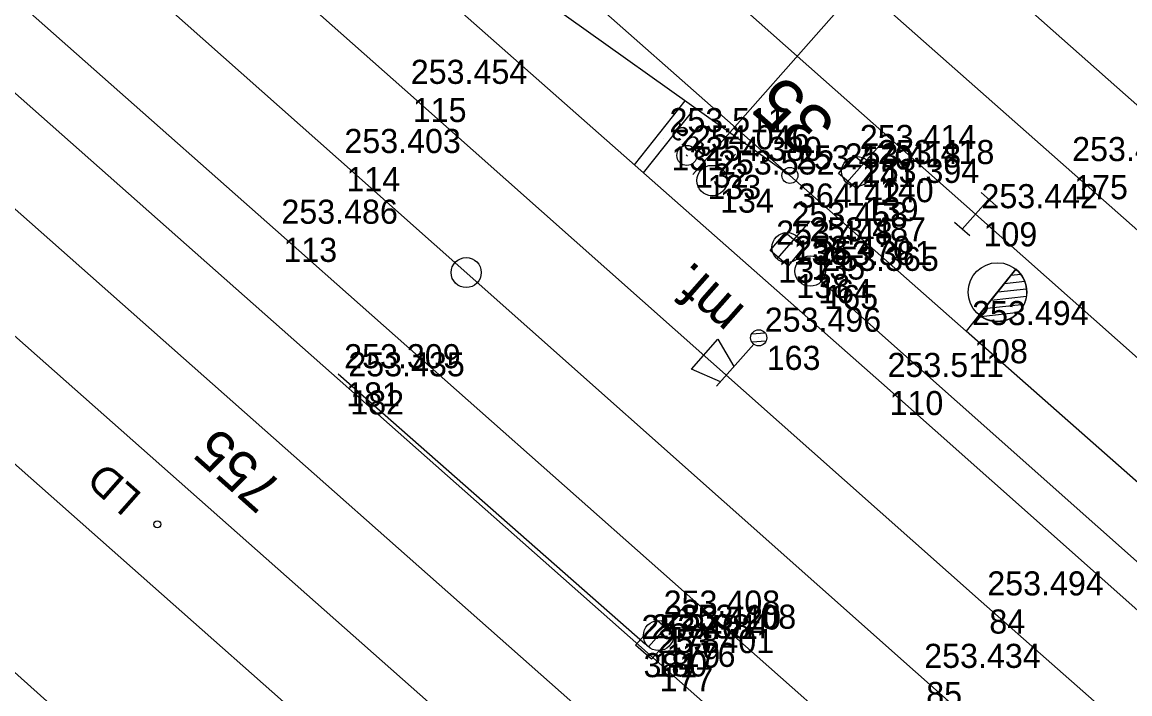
# Model space of a CAD drawing. Extents: x -496688 to -495455, y -1089309 to -1088026.
# Drawn here: x -496161.2 to -496106, y -1088523.5 to -1088490 of the extents above; entities that cross this region are included whole.
import ezdxf

# ---------------------------------------------------------------- set-up
doc = ezdxf.new("R2010")
doc.units = 0
for name, color, linetype in [('Vrstva 1', 7, 'Continuous'), ('Vrstva 12', 7, 'Continuous'), ('Vrstva 2', 7, 'Continuous'), ('Vrstva 23', 7, 'Continuous'), ('Vrstva 3', 7, 'Continuous'), ('Vrstva 33', 7, 'Continuous'), ('Vrstva 36', 7, 'Continuous'), ('Vrstva 47', 7, 'Continuous'), ('Vrstva 57', 7, 'Continuous'), ('Vrstva 59', 7, 'Continuous'), ('Vrstva 6', 7, 'Continuous'), ('Vrstva 60', 7, 'Continuous'), ('Vrstva 61', 7, 'Continuous'), ('Vrstva 7', 7, 'Continuous')]:
    doc.layers.add(name, color=color, linetype=linetype)

msp = doc.modelspace()

# ---------------------------------------------------------------- linework, layer by layer
at = {"layer": 'Vrstva 1'}
for points in [[(-496098.321, -1088532.14), (-496113.381, -1088518.859), (-496142.095, -1088493.38), (-496184.385, -1088455.93), (-496196.867, -1088444.876), (-496209.306, -1088433.861), (-496213.249, -1088430.329), (-496225.685, -1088419.311), (-496238.055, -1088408.352), (-496252.739, -1088395.349), (-496269.088, -1088380.829), (-496284.933, -1088366.798), (-496289.774, -1088362.518), (-496304.914, -1088349.103), (-496331.751, -1088325.354), (-496382.404, -1088280.635)], [(-496101.697, -1088535.642), (-496116.65, -1088522.36), (-496145.401, -1088496.824), (-496192.559, -1088454.988), (-496206.347, -1088442.759), (-496213.463, -1088436.447), (-496216.342, -1088433.89), (-496225.123, -1088426.139), (-496237.731, -1088415.01), (-496248.348, -1088406.17), (-496261.601, -1088395.991)], [(-495794.281, -1088769.662), (-495806.718, -1088758.644), (-495819.114, -1088747.662), (-495828.107, -1088739.648), (-495840.608, -1088728.579), (-495852.984, -1088717.621), (-495860.029, -1088711.42), (-495872.461, -1088700.397), (-495884.955, -1088689.319), (-495893.533, -1088681.721), (-495913.179, -1088664.263), (-495947.105, -1088634.191), (-495952.116, -1088629.76), (-495964.613, -1088618.686), (-495984.901, -1088600.717), (-495997.336, -1088589.715), (-496002.819, -1088584.884), (-496021.751, -1088568.167), (-496024.418, -1088565.811), (-496062.504, -1088532.205), (-496086.773, -1088510.767), (-496106.199, -1088493.629), (-496127.249, -1088474.987), (-496164.633, -1088441.927)], [(-496122.914, -1088497.64), (-496138.079, -1088486.834), (-496145.352, -1088481.632), (-496159.797, -1088471.287), (-496169.319, -1088464.468), (-496183.248, -1088454.488), (-496196.867, -1088444.876)], [(-495916.136, -1088667.962), (-495923.285, -1088661.656), (-495935.688, -1088650.668), (-495948.162, -1088639.613), (-495977.755, -1088613.379), (-495990.206, -1088602.384), (-496002.656, -1088591.386), (-496007.627, -1088586.973), (-496020.065, -1088575.979), (-496027.948, -1088569.009), (-496033.091, -1088564.46), (-496045.526, -1088553.442), (-496057.996, -1088542.394), (-496059.439, -1088541.128), (-496090.012, -1088514.139), (-496109.155, -1088497.226), (-496130.335, -1088478.506), (-496167.718, -1088445.393)], [(-496025.85, -1088577.242), (-496038.324, -1088566.223), (-496068.822, -1088539.309), (-496081.287, -1088528.275), (-496093.728, -1088517.263), (-496094.813, -1088516.301), (-496113.671, -1088499.573), (-496133.331, -1088482.129), (-496170.85, -1088448.892)], [(-496095.727, -1088521.63), (-496114.138, -1088505.396), (-496122.914, -1088497.64), (-496136.308, -1088485.801), (-496152.389, -1088471.491), (-496161.166, -1088463.737)], [(-496104.138, -1088539.66), (-496119.75, -1088525.847), (-496148.539, -1088500.347), (-496166.653, -1088484.334), (-496175.44, -1088476.59), (-496187.907, -1088465.601)], [(-496099.2, -1088524.988), (-496118.349, -1088507.977), (-496145.851, -1088483.696), (-496159.797, -1088471.287)], [(-496128.341, -1088534.994), (-496173.425, -1088495.115)], [(-496125.191, -1088531.455), (-496163.844, -1088497.265)], [(-496131.495, -1088538.579), (-496169.855, -1088504.648)]]:
    msp.add_lwpolyline(points, dxfattribs=at)
at = {"layer": 'Vrstva 12'}
for points in [[(-496120.488, -1088497.542), (-496119.728, -1088496.624), (-496118.831, -1088497.375), (-496119.584, -1088498.313), (-496120.488, -1088497.542)], [(-496123.895, -1088501.385), (-496123.131, -1088500.48), (-496122.24, -1088501.226), (-496122.991, -1088502.148), (-496123.895, -1088501.385)], [(-496130.602, -1088521.03), (-496129.5, -1088519.815), (-496128.699, -1088520.518), (-496129.801, -1088521.733), (-496130.602, -1088521.03)]]:
    msp.add_lwpolyline(points, dxfattribs=at)
at = {"layer": 'Vrstva 2'}
for p, q in [((-496113.495, -1088504.593), (-496111.658, -1088502.314)), ((-496111.658, -1088502.314), (-496113.494, -1088504.594)), ((-496111.897, -1088502.61), (-496111.423, -1088502.558)), ((-496112.229, -1088503.023), (-496111.22, -1088502.914)), ((-496112.896, -1088503.849), (-496111.13, -1088503.659)), ((-496112.562, -1088503.436), (-496111.126, -1088503.281)), ((-496113.229, -1088504.261), (-496111.242, -1088504.047)), ((-496113.496, -1088504.594), (-496114.138, -1088505.396)), ((-496113.494, -1088504.594), (-496113.495, -1088504.593)), ((-496113.402, -1088504.658), (-496111.514, -1088504.454))]:
    msp.add_line(p, q, dxfattribs=at)
for points in [[(-496114.138, -1088505.396), (-496122.914, -1088497.64), (-496136.308, -1088485.801)], [(-496122.914, -1088497.64), (-496138.079, -1088486.834)]]:
    msp.add_lwpolyline(points, dxfattribs=at)
for centre, radius in [((-496122.914, -1088497.64), 0.4), ((-496112.57, -1088503.448), 1.462)]:
    msp.add_circle(centre, radius, dxfattribs=at)
msp.add_arc((-496112.577, -1088503.453), 1.464, 231.1743, 51.1351, dxfattribs=at)
at = {"layer": 'Vrstva 23'}
msp.add_lwpolyline([(-496122.209, -1088528.323), (-496134.209, -1088541.938), (-496150.053, -1088527.973), (-496152.367, -1088530.599), (-496181.619, -1088504.378), (-496167.429, -1088488.299), (-496122.209, -1088528.323)], dxfattribs=at)
at = {"layer": 'Vrstva 3'}
for p, q in [((-496112.634, -1088499.155), (-496113.383, -1088498.493)), ((-496114.333, -1088500.322), (-496113.009, -1088498.824)), ((-496113.959, -1088500.653), (-496114.708, -1088499.991))]:
    msp.add_line(p, q, dxfattribs=at)
at = {"layer": 'Vrstva 33'}
for p, q in [((-496127.819, -1088507.294), (-496126.495, -1088505.796)), ((-496126.495, -1088505.796), (-496125.702, -1088507.164)), ((-496124.139, -1088505.499), (-496124.819, -1088505.541)), ((-496126.563, -1088508.138), (-496124.714, -1088506.041)), ((-496124.105, -1088505.898), (-496124.8, -1088505.941)), ((-496126.364, -1088507.913), (-496127.819, -1088507.294))]:
    msp.add_line(p, q, dxfattribs=at)
msp.add_circle((-496124.466, -1088505.726), 0.401, dxfattribs=at)
msp.add_circle((-496124.466, -1088505.726), 0.401, dxfattribs=at)
at = {"layer": 'Vrstva 36'}
for p, q in [((-496126.29, -1088497.328), (-496125.63, -1088496.577)), ((-496121.4, -1088501.839), (-496120.738, -1088501.09))]:
    msp.add_line(p, q, dxfattribs=at)
msp.add_lwpolyline([(-495982.001, -1088613.178), (-495986.312, -1088609.628), (-495992.007, -1088605.254), (-495994.985, -1088602.919), (-496012.279, -1088590.201), (-496017.631, -1088586.544), (-496026.239, -1088581.024), (-496029.453, -1088578.634), (-496040.554, -1088570.808), (-496043.73, -1088568.341), (-496063.489, -1088552.926), (-496089.159, -1088531.511), (-496093.567, -1088527.59), (-496121.596, -1088502.694)], dxfattribs=at)
for centre in [(-496126.791, -1088497.894), (-496121.903, -1088502.404)]:
    msp.add_circle(centre, 0.757, dxfattribs=at)
at = {"layer": 'Vrstva 47'}
for p, q in [((-496120.089, -1088498.002), (-496118.429, -1088496.132)), ((-496123.553, -1088501.795), (-496121.899, -1088499.922)), ((-496129.955, -1088521.12), (-496128.299, -1088519.247))]:
    msp.add_line(p, q, dxfattribs=at)
msp.add_lwpolyline([(-496130.108, -1088520.998), (-496145.412, -1088507.543)], dxfattribs=at)
for centre in [(-496119.591, -1088497.441), (-496123.057, -1088501.233), (-496129.458, -1088520.558)]:
    msp.add_circle(centre, 0.75, dxfattribs=at)
at = {"layer": 'Vrstva 59'}
msp.add_circle((-496154.417, -1088515.016), 0.175, dxfattribs=at)
at = {"layer": 'Vrstva 6'}
for p, q in [((-496127.419, -1088497.214), (-496021.846, -1088377.607)), ((-496127.088, -1088496.84), (-496127.75, -1088497.588))]:
    msp.add_line(p, q, dxfattribs=at)
at = {"layer": 'Vrstva 60'}
for p, q in [((-496142.095, -1088493.38), (-496142.095, -1088493.38)), ((-496142.095, -1088493.38), (-496142.095, -1088493.38)), ((-496106.199, -1088493.629), (-496106.199, -1088493.629)), ((-496106.199, -1088493.629), (-496106.199, -1088493.629)), ((-496129.211, -1088495.785), (-496129.211, -1088495.785)), ((-496129.211, -1088495.785), (-496129.211, -1088495.785)), ((-496145.401, -1088496.824), (-496145.401, -1088496.824)), ((-496145.401, -1088496.824), (-496145.401, -1088496.824)), ((-496128.043, -1088496.643), (-496128.043, -1088496.643)), ((-496128.043, -1088496.643), (-496128.043, -1088496.643)), ((-496119.728, -1088496.624), (-496119.728, -1088496.624)), ((-496119.728, -1088496.624), (-496119.728, -1088496.624)), ((-496127.419, -1088497.214), (-496127.419, -1088497.214)), ((-496127.419, -1088497.214), (-496127.419, -1088497.214)), ((-496120.488, -1088497.542), (-496120.488, -1088497.542)), ((-496120.488, -1088497.542), (-496120.488, -1088497.542)), ((-496118.831, -1088497.375), (-496118.831, -1088497.375)), ((-496118.831, -1088497.375), (-496118.831, -1088497.375)), ((-496109.155, -1088497.226), (-496109.155, -1088497.226)), ((-496109.155, -1088497.226), (-496109.155, -1088497.226)), ((-496126.791, -1088497.895), (-496126.791, -1088497.895)), ((-496126.791, -1088497.895), (-496126.791, -1088497.895)), ((-496122.914, -1088497.64), (-496122.914, -1088497.64)), ((-496122.914, -1088497.64), (-496122.914, -1088497.64)), ((-496119.584, -1088498.313), (-496119.584, -1088498.313)), ((-496119.584, -1088498.313), (-496119.584, -1088498.313)), ((-496113.671, -1088499.573), (-496113.671, -1088499.573)), ((-496113.671, -1088499.573), (-496113.671, -1088499.573)), ((-496148.539, -1088500.347), (-496148.539, -1088500.347)), ((-496148.539, -1088500.347), (-496148.539, -1088500.347)), ((-496123.131, -1088500.48), (-496123.131, -1088500.48)), ((-496123.131, -1088500.48), (-496123.131, -1088500.48)), ((-496123.895, -1088501.385), (-496123.895, -1088501.385)), ((-496123.895, -1088501.385), (-496123.895, -1088501.385)), ((-496122.24, -1088501.226), (-496122.24, -1088501.226)), ((-496122.24, -1088501.226), (-496122.24, -1088501.226)), ((-496122.991, -1088502.148), (-496122.991, -1088502.148)), ((-496122.991, -1088502.148), (-496122.991, -1088502.148)), ((-496121.903, -1088502.405), (-496121.903, -1088502.405)), ((-496121.903, -1088502.405), (-496121.903, -1088502.405)), ((-496121.596, -1088502.694), (-496121.596, -1088502.694)), ((-496121.596, -1088502.694), (-496121.596, -1088502.694)), ((-496124.466, -1088505.726), (-496124.466, -1088505.726)), ((-496124.466, -1088505.726), (-496124.466, -1088505.726)), ((-496114.138, -1088505.396), (-496114.138, -1088505.396)), ((-496114.138, -1088505.396), (-496114.138, -1088505.396)), ((-496145.412, -1088507.543), (-496145.412, -1088507.543)), ((-496145.412, -1088507.543), (-496145.412, -1088507.543)), ((-496145.205, -1088507.946), (-496145.205, -1088507.946)), ((-496145.205, -1088507.946), (-496145.205, -1088507.946)), ((-496118.349, -1088507.977), (-496118.349, -1088507.977)), ((-496118.349, -1088507.977), (-496118.349, -1088507.977)), ((-496113.381, -1088518.859), (-496113.381, -1088518.859)), ((-496113.381, -1088518.859), (-496113.381, -1088518.859)), ((-496129.5, -1088519.815), (-496129.5, -1088519.815)), ((-496129.5, -1088519.815), (-496129.5, -1088519.815)), ((-496129.458, -1088520.558), (-496129.458, -1088520.558)), ((-496129.458, -1088520.558), (-496129.458, -1088520.558)), ((-496128.699, -1088520.518), (-496128.699, -1088520.518)), ((-496128.699, -1088520.518), (-496128.699, -1088520.518)), ((-496130.602, -1088521.03), (-496130.602, -1088521.03)), ((-496130.602, -1088521.03), (-496130.602, -1088521.03)), ((-496130.108, -1088520.998), (-496130.108, -1088520.998)), ((-496130.108, -1088520.998), (-496130.108, -1088520.998)), ((-496129.801, -1088521.733), (-496129.801, -1088521.733)), ((-496129.801, -1088521.733), (-496129.801, -1088521.733)), ((-496116.523, -1088522.468), (-496116.523, -1088522.468)), ((-496116.523, -1088522.468), (-496116.523, -1088522.468))]:
    msp.add_line(p, q, dxfattribs=at)
at = {"layer": 'Vrstva 7'}
for p, q in [((-496130.651, -1088497.116), (-496128.121, -1088493.93)), ((-496130.2, -1088497.514), (-496127.631, -1088494.279)), ((-496128.006, -1088496.676), (-496128.08, -1088496.61))]:
    msp.add_line(p, q, dxfattribs=at)
for centre, radius in [((-496128.043, -1088496.643), 0.5), ((-496139.035, -1088502.478), 0.75)]:
    msp.add_circle(centre, radius, dxfattribs=at)

# ---------------------------------------------------------------- texts
at = {"layer": 'Vrstva 2'}
msp.add_text('35', height=2.5, rotation=138.5391, dxfattribs=at).set_placement((-496120.519, -1088494.992))
at = {"layer": 'Vrstva 23'}
msp.add_text('LD', height=1.5, rotation=138.6068, dxfattribs=at).set_placement((-496155.12, -1088513.541))
at = {"layer": 'Vrstva 33'}
msp.add_text('mf.', height=2, rotation=138.5279, dxfattribs=at).set_placement((-496125.068, -1088504.282))
at = {"layer": 'Vrstva 57'}
msp.add_text('755', height=2, rotation=138.4179, dxfattribs=at).set_placement((-496148.085, -1088513.068))
at = {"layer": 'Vrstva 6'}
msp.add_text('aqa', height=1, rotation=138.5281, dxfattribs=at).set_placement((-496126.757, -1088496.465))
at = {"layer": 'Vrstva 60'}
for s, p in [('115', (-496141.695, -1088494.98)), ('115', (-496141.695, -1088494.98)), ('131', (-496128.811, -1088497.385)), ('131', (-496128.811, -1088497.385)), ('132', (-496127.643, -1088498.243)), ('132', (-496127.643, -1088498.243)), ('141', (-496119.328, -1088498.224)), ('141', (-496119.328, -1088498.224)), ('114', (-496145.001, -1088498.424)), ('114', (-496145.001, -1088498.424)), ('133', (-496127.019, -1088498.814)), ('133', (-496127.019, -1088498.814)), ('364', (-496122.514, -1088499.24)), ('364', (-496122.514, -1088499.24)), ('142', (-496120.088, -1088499.142)), ('142', (-496120.088, -1088499.142)), ('140', (-496118.431, -1088498.975)), ('140', (-496118.431, -1088498.975)), ('175', (-496108.755, -1088498.826)), ('175', (-496108.755, -1088498.826)), ('134', (-496126.391, -1088499.495)), ('134', (-496126.391, -1088499.495)), ('139', (-496119.184, -1088499.913)), ('139', (-496119.184, -1088499.913)), ('109', (-496113.271, -1088501.173)), ('109', (-496113.271, -1088501.173)), ('113', (-496148.139, -1088501.947)), ('113', (-496148.139, -1088501.947)), ('136', (-496122.731, -1088502.08)), ('136', (-496122.731, -1088502.08)), ('137', (-496123.495, -1088502.985)), ('137', (-496123.495, -1088502.985)), ('135', (-496121.84, -1088502.826)), ('135', (-496121.84, -1088502.826)), ('138', (-496122.591, -1088503.748)), ('138', (-496122.591, -1088503.748)), ('164', (-496121.503, -1088504.005)), ('164', (-496121.503, -1088504.005)), ('165', (-496121.196, -1088504.294)), ('165', (-496121.196, -1088504.294)), ('108', (-496113.738, -1088506.996)), ('108', (-496113.738, -1088506.996)), ('163', (-496124.066, -1088507.326)), ('163', (-496124.066, -1088507.326)), ('181', (-496145.012, -1088509.143)), ('181', (-496145.012, -1088509.143)), ('182', (-496144.805, -1088509.546)), ('182', (-496144.805, -1088509.546)), ('110', (-496117.949, -1088509.577)), ('110', (-496117.949, -1088509.577)), ('84', (-496112.981, -1088520.459)), ('84', (-496112.981, -1088520.459)), ('178', (-496129.1, -1088521.415)), ('178', (-496129.1, -1088521.415)), ('179', (-496129.058, -1088522.158)), ('179', (-496129.058, -1088522.158)), ('176', (-496128.299, -1088522.118)), ('176', (-496128.299, -1088522.118)), ('381', (-496130.202, -1088522.63)), ('381', (-496130.202, -1088522.63)), ('180', (-496129.708, -1088522.598)), ('180', (-496129.708, -1088522.598)), ('177', (-496129.401, -1088523.333)), ('177', (-496129.401, -1088523.333)), ('85', (-496116.123, -1088524.068)), ('85', (-496116.123, -1088524.068))]:
    msp.add_text(s, height=1.2, dxfattribs=at).set_placement(p)
at = {"layer": 'Vrstva 61'}
for s, p in [('253.454', (-496141.795, -1088493.08)), ('253.454', (-496141.795, -1088493.08)), ('253.511', (-496128.911, -1088495.485)), ('253.511', (-496128.911, -1088495.485)), ('253.403', (-496145.101, -1088496.524)), ('253.403', (-496145.101, -1088496.524)), ('254.046', (-496127.743, -1088496.343)), ('254.046', (-496127.743, -1088496.343)), ('253.414', (-496119.428, -1088496.324)), ('253.414', (-496119.428, -1088496.324)), ('254.380', (-496127.119, -1088496.914)), ('254.380', (-496127.119, -1088496.914)), ('253.418', (-496118.531, -1088497.075)), ('253.418', (-496118.531, -1088497.075)), ('253.420', (-496108.855, -1088496.926)), ('253.420', (-496108.855, -1088496.926)), ('253.552', (-496126.491, -1088497.595)), ('253.552', (-496126.491, -1088497.595)), ('253.470', (-496122.614, -1088497.34)), ('253.470', (-496122.614, -1088497.34)), ('253.418', (-496120.188, -1088497.242)), ('253.418', (-496120.188, -1088497.242)), ('253.394', (-496119.284, -1088498.013)), ('253.394', (-496119.284, -1088498.013)), ('253.442', (-496113.371, -1088499.273)), ('253.442', (-496113.371, -1088499.273)), ('253.486', (-496148.239, -1088500.047)), ('253.486', (-496148.239, -1088500.047)), ('253.458', (-496122.831, -1088500.18)), ('253.458', (-496122.831, -1088500.18)), ('253.487', (-496121.94, -1088500.926)), ('253.487', (-496121.94, -1088500.926)), ('253.448', (-496123.595, -1088501.085)), ('253.448', (-496123.595, -1088501.085)), ('253.470', (-496122.691, -1088501.848)), ('253.470', (-496122.691, -1088501.848)), ('253.381', (-496121.603, -1088502.105)), ('253.381', (-496121.603, -1088502.105)), ('253.365', (-496121.296, -1088502.394)), ('253.365', (-496121.296, -1088502.394)), ('253.496', (-496124.166, -1088505.426)), ('253.496', (-496124.166, -1088505.426)), ('253.494', (-496113.838, -1088505.096)), ('253.494', (-496113.838, -1088505.096)), ('253.309', (-496145.112, -1088507.243)), ('253.309', (-496145.112, -1088507.243)), ('253.435', (-496144.905, -1088507.646)), ('253.435', (-496144.905, -1088507.646)), ('253.511', (-496118.049, -1088507.677)), ('253.511', (-496118.049, -1088507.677)), ('253.494', (-496113.081, -1088518.559)), ('253.494', (-496113.081, -1088518.559)), ('253.408', (-496129.2, -1088519.515)), ('253.408', (-496129.2, -1088519.515)), ('253.420', (-496129.158, -1088520.258)), ('253.420', (-496129.158, -1088520.258)), ('253.408', (-496128.399, -1088520.218)), ('253.408', (-496128.399, -1088520.218)), ('253.401', (-496130.302, -1088520.73)), ('253.401', (-496130.302, -1088520.73)), ('253.384', (-496129.808, -1088520.698)), ('253.384', (-496129.808, -1088520.698)), ('253.401', (-496129.501, -1088521.433)), ('253.401', (-496129.501, -1088521.433)), ('253.434', (-496116.223, -1088522.168)), ('253.434', (-496116.223, -1088522.168))]:
    msp.add_text(s, height=1.2, dxfattribs=at).set_placement(p)

doc.saveas('drawing.dxf')
